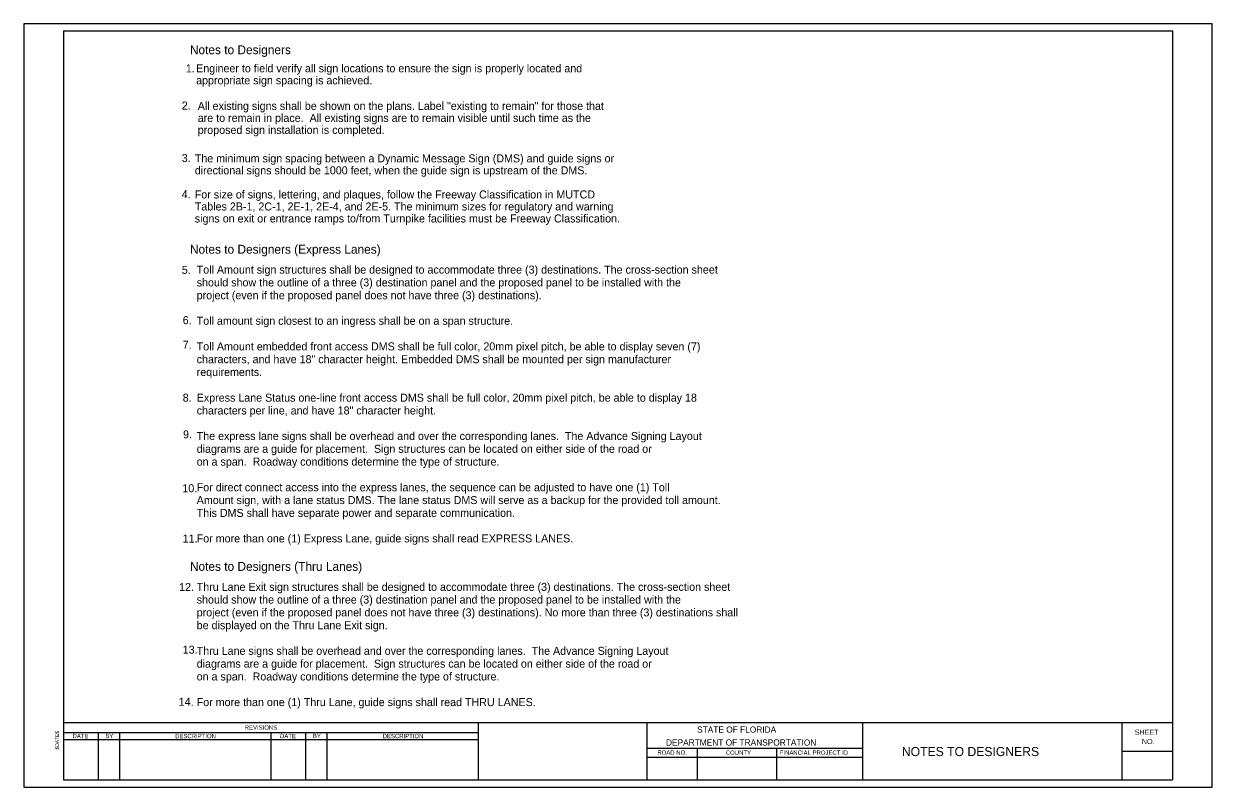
# Model space of a CAD drawing. Extents: x 17889077 to 17890097, y 17891867 to 17892522.
import ezdxf

# ---------------------------------------------------------------- set-up
doc = ezdxf.new("R2010")
doc.units = 0
for name, color, linetype in [('PlotBorder_dp', 7, 'Continuous'), ('SheetBorder_dp', 7, 'Continuous'), ('SheetLines_dp', 7, 'Continuous'), ('TextLabel', 7, 'Continuous'), ('TextMinor', 7, 'Continuous'), ('TextMisc', 7, 'Continuous')]:
    doc.layers.add(name, color=color, linetype=linetype)

msp = doc.modelspace()

# ---------------------------------------------------------------- linework, layer by layer
at = {"layer": 'PlotBorder_dp'}
msp.add_lwpolyline([(17889076.8, 17891866.6), (17890096.8, 17891866.6), (17890096.8, 17892521.8), (17889076.8, 17892521.8)], close=True, dxfattribs=at)
at = {"layer": 'SheetBorder_dp'}
for p, q in [((17889110.8, 17892515.7), (17889110.8, 17891872.8)), ((17889110.8, 17892515.7), (17890062.8, 17892515.7)), ((17890062.8, 17892515.7), (17890062.8, 17891872.8)), ((17889110.8, 17891922.2), (17890062.8, 17891922.2)), ((17889110.8, 17891872.8), (17890062.8, 17891872.8))]:
    msp.add_line(p, q, dxfattribs=at)
at = {"layer": 'SheetLines_dp'}
for p, q in [((17889466.9, 17891922.2), (17889466.9, 17891872.8)), ((17889611.5, 17891922.2), (17889611.5, 17891872.8)), ((17889797, 17891872.8), (17889797, 17891922.2)), ((17890019.5, 17891872.8), (17890019.5, 17891922.2)), ((17889110.8, 17891913.6), (17889466.9, 17891913.6)), ((17889140.5, 17891913.6), (17889140.5, 17891872.8)), ((17889159, 17891913.6), (17889159, 17891872.8)), ((17889288.8, 17891913.6), (17889288.8, 17891872.8)), ((17889318.5, 17891913.6), (17889318.5, 17891872.8)), ((17889337, 17891913.6), (17889337, 17891872.8)), ((17889110.8, 17891907.4), (17889466.9, 17891907.4)), ((17889611.5, 17891900), (17889797, 17891900)), ((17889611.5, 17891892.5), (17889797, 17891892.5)), ((17889654.8, 17891900), (17889654.8, 17891872.8)), ((17889722.8, 17891900), (17889722.8, 17891872.8)), ((17890019.5, 17891897.5), (17890062.8, 17891897.5))]:
    msp.add_line(p, q, dxfattribs=at)

# ---------------------------------------------------------------- texts
at = {"layer": 'TextLabel'}
for s, height, p in [('Notes to Designers', 7.62, (17889219.4, 17892495.7)), ('1.', 6.87, (17889215.9, 17892480.1)), ('  Engineer to field verify all sign locations to ensure the sign is properly located and', 6.868, (17889219.6, 17892480.2)), ('  appropriate sign spacing is achieved.', 6.868, (17889219.6, 17892469.9)), ('2.', 6.87, (17889212.4, 17892448.2)), ('  All existing signs shall be shown on the plans. Label "existing to remain" for those that ', 6.868, (17889221, 17892447.9)), ('  are to remain in place.  All existing signs are to remain visible until such time as the', 6.868, (17889221, 17892437.6)), ('  proposed sign installation is completed.', 6.868, (17889221, 17892427.3)), ('3.', 6.87, (17889212.4, 17892403.2)), (' The minimum sign spacing between a Dynamic Message Sign (DMS) and guide signs or', 6.868, (17889221, 17892402.9)), (' directional signs should be 1000 feet, when the guide sign is upstream of the DMS.', 6.868, (17889221, 17892392.6)), ('4.', 6.87, (17889212.4, 17892372.2)), (' For size of signs, lettering, and plaques, follow the Freeway Classification in MUTCD', 6.868, (17889221, 17892371.9)), (' Tables 2B-1, 2C-1, 2E-1, 2E-4, and 2E-5. The minimum sizes for regulatory and warning', 6.868, (17889221, 17892361.6)), (' signs on exit or entrance ramps to/from Turnpike facilities must be Freeway Classification.', 6.868, (17889221, 17892351.3)), ('Notes to Designers (Express Lanes)', 7.62, (17889219.4, 17892324.5)), ('5.', 6.87, (17889212.4, 17892307.2)), ('  Toll Amount sign structures shall be designed to accommodate three (3) destinations. The cross-section sheet', 6.8678, (17889220.1, 17892307.4)), ('  should show the outline of a three (3) destination panel and the proposed panel to be installed with the', 6.8678, (17889220.1, 17892296.4)), ('  project (even if the proposed panel does not have three (3) destinations).  ', 6.868, (17889220.1, 17892285.4)), ('6.', 6.87, (17889213.2, 17892264)), ('  Toll amount sign closest to an ingress shall be on a span structure.', 6.868, (17889220.1, 17892263.5)), ('7.', 6.87, (17889213.2, 17892242.9)), ('  Toll Amount embedded front access DMS shall be full color, 20mm pixel pitch, be able to display seven (7)', 6.8678, (17889220.1, 17892241.5)), ('  characters, and have 18" character height. Embedded DMS shall be mounted per sign manufacturer', 6.868, (17889220.1, 17892230.5)), ('  requirements.', 6.868, (17889220.1, 17892219.5)), ('8.', 6.87, (17889213.2, 17892197.5)), ('  Express Lane Status one-line front access DMS shall be full color, 20mm pixel pitch, be able to display 18', 6.8678, (17889220.1, 17892197.5)), ('  characters per line, and have 18" character height.', 6.868, (17889220.1, 17892186.5)), ('9.', 6.87, (17889213.5, 17892166)), ('  The express lane signs shall be overhead and over the corresponding lanes.  The Advance Signing Layout', 6.8678, (17889220.1, 17892164.6)), ('  diagrams are a guide for placement.  Sign structures can be located on either side of the road or', 6.868, (17889220.1, 17892153.6)), ('  on a span.  Roadway conditions determine the type of structure.', 6.868, (17889220.1, 17892142.6)), ('10.', 6.87, (17889212.9, 17892119.8)), ('  For direct connect access into the express lanes, the sequence can be adjusted to have one (1) Toll', 6.8678, (17889220.1, 17892120.6)), ('  Amount sign, with a lane status DMS. The lane status DMS will serve as a backup for the provided toll amount.', 6.8678, (17889220.1, 17892109.6)), ('  This DMS shall have separate power and separate communication.', 6.868, (17889220.1, 17892098.6)), ('11.', 6.87, (17889213.1, 17892076.6)), ('  For more than one (1) Express Lane, guide signs shall read EXPRESS LANES.', 6.868, (17889220.1, 17892076.7)), ('Notes to Designers (Thru Lanes)', 7.62, (17889219.4, 17892052.3)), ('12.', 6.87, (17889210.1, 17892035)), ('  Thru Lane Exit sign structures shall be designed to accommodate three (3) destinations. The cross-section sheet', 6.8678, (17889220.1, 17892035.1)), ('  should show the outline of a three (3) destination panel and the proposed panel to be installed with the', 6.8678, (17889220.1, 17892024.2)), ('  project (even if the proposed panel does not have three (3) destinations). No more than three (3) destinations shall', 6.8678, (17889220.1, 17892013.2)), ('  be displayed on the Thru Lane Exit sign.', 6.868, (17889220.1, 17892002.2)), ('13.', 6.87, (17889213.2, 17891981.2)), ('  Thru Lane signs shall be overhead and over the corresponding lanes.  The Advance Signing Layout', 6.868, (17889220.1, 17891980.2)), ('  diagrams are a guide for placement.  Sign structures can be located on either side of the road or', 6.868, (17889220.1, 17891969.2)), ('  on a span.  Roadway conditions determine the type of structure.', 6.868, (17889220.1, 17891958.2)), ('14.', 6.87, (17889209.7, 17891936.5)), ('  For more than one (1) Thru Lane, guide signs shall read THRU LANES.', 6.868, (17889220.1, 17891936.2))]:
    msp.add_text(s, height=height, dxfattribs=at).set_placement(p)
at = {"layer": 'TextMinor'}
msp.add_text('$DATE$', height=3.03, rotation=90, dxfattribs=at).set_placement((17889106.9, 17891899))
at = {"layer": 'TextMisc'}
for s, height, rotation, p in [('DATE', 3.71, 359.8693, (17889118.6, 17891908.7)), ('DESCRIPTION', 3.708, 0.0498, (17889206.7, 17891908.6)), ('DATE', 3.71, 359.8693, (17889296.7, 17891908.7)), ('DESCRIPTION', 3.708, 0.0498, (17889384.8, 17891908.6)), ('SHEET', 4.45, 359.8607, (17890030.3, 17891911.6)), ('NO.', 4.45, 359.8607, (17890036.4, 17891903.6))]:
    msp.add_text(s, height=height, rotation=rotation, dxfattribs=at).set_placement(p)
for s, height, p in [('BY', 3.71, (17889146.8, 17891908.7)), ('REVISIONS', 3.71, (17889266.4, 17891916)), ('BY', 3.71, (17889324.9, 17891908.7)), ('STATE OF FLORIDA', 5.341, (17889654.7, 17891913.4)), ('DEPARTMENT OF TRANSPORTATION', 5.341, (17889628, 17891902.3)), ('ROAD NO.', 3.71, (17889620.6, 17891894.5)), ('COUNTY', 3.71, (17889679.3, 17891894.4)), ('FINANCIAL PROJECT ID', 3.709, (17889725.6, 17891894.4)), ('NOTES TO DESIGNERS', 7.812, (17889830.4, 17891893.3)), ('$USER$', 0.0625, (17889907.2, 17891896.5)), ('$DATE$', 0.0625, (17889908, 17891896.5)), ('$TIME$', 0.0625, (17889908.9, 17891896.5))]:
    msp.add_text(s, height=height, dxfattribs=at).set_placement(p)

doc.saveas('drawing.dxf')
